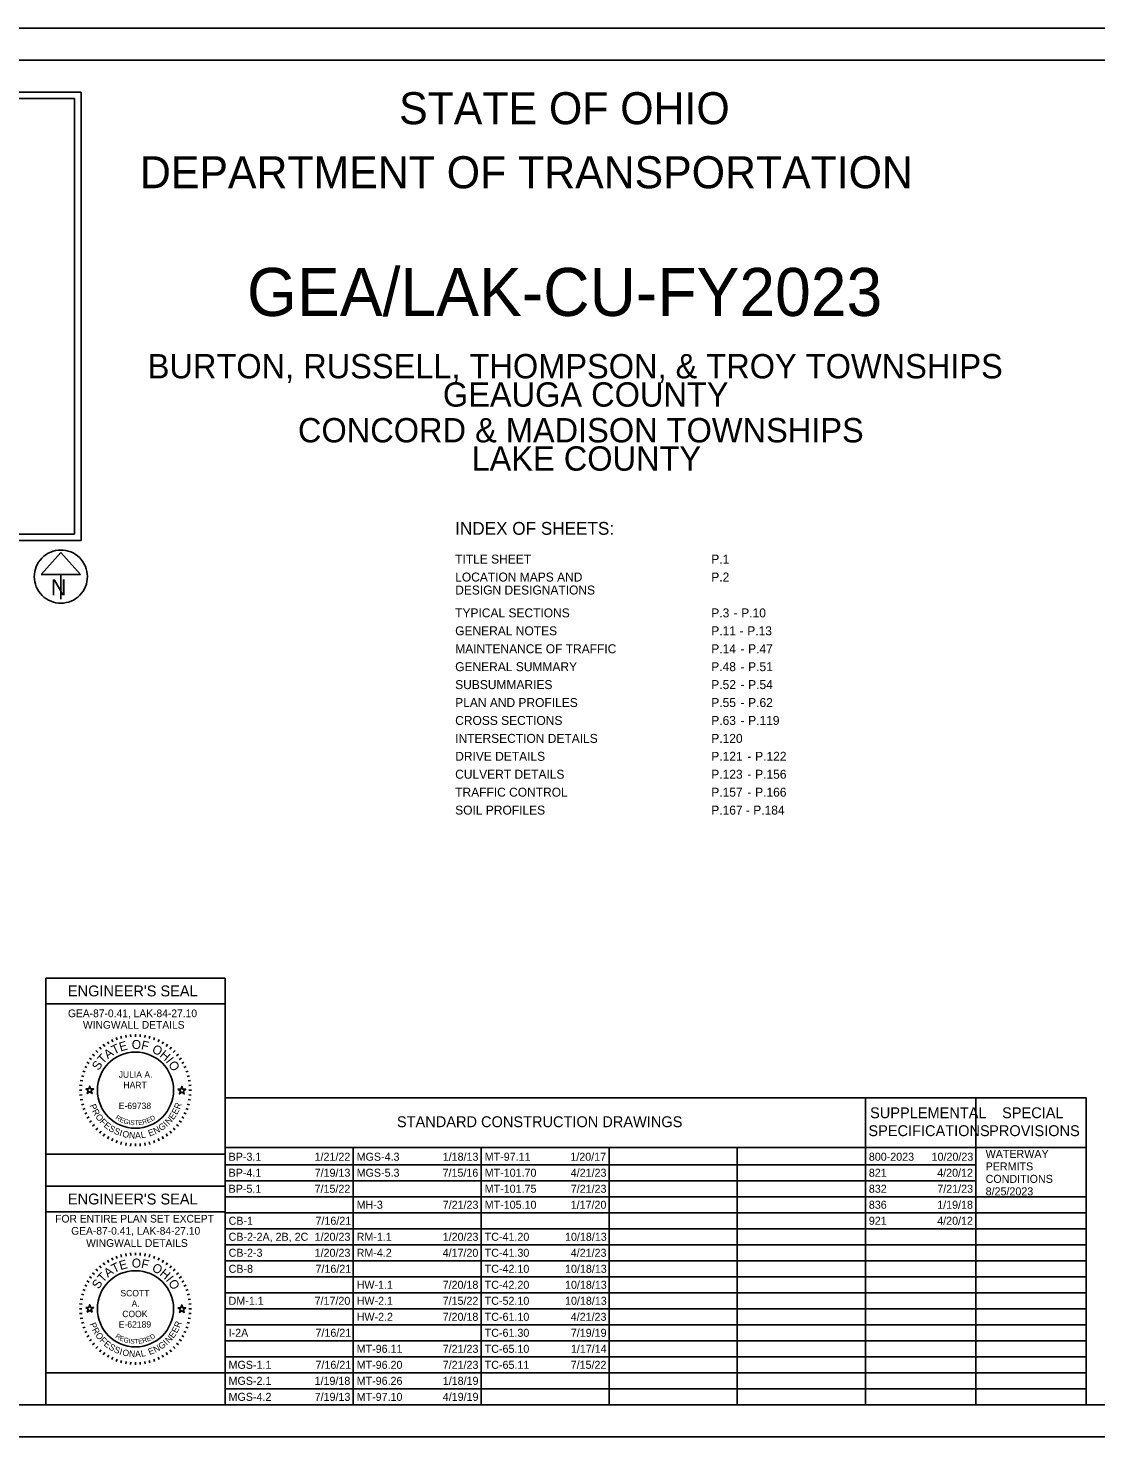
# Model space of a CAD drawing. Extents: x -0.3 to 41.5, y 0 to 22.
# Drawn here: x 8.17 to 24.85, y 0 to 22 of the extents above; entities that cross this region are included whole.
import ezdxf

# ---------------------------------------------------------------- set-up
doc = ezdxf.new("R2010")
doc.units = 0
for name, color, linetype in [('GM_X_Section', 7, 'Continuous'), ('SH_Border', 7, 'Continuous'), ('SH_Cut_Line', 7, 'Continuous'), ('SH_Data', 7, 'Continuous')]:
    doc.layers.add(name, color=color, linetype=linetype)

msp = doc.modelspace()

# ---------------------------------------------------------------- linework, layer by layer
at = {"layer": 'SH_Border'}
msp.add_lwpolyline([(0, 0), (34, 0), (34, 22), (0, 22)], close=True, dxfattribs=at)
at = {"layer": 'SH_Cut_Line'}
for p, q in [((2, 21), (9, 21)), ((2.1, 20.9), (8.9, 20.9)), ((8.9, 20.9), (8.9, 14.1)), ((9, 21), (9, 14)), ((2.1, 14.1), (8.9, 14.1)), ((2, 14), (9, 14)), ((8.685, 13.809), (8.377, 13.468)), ((8.992, 13.468), (8.685, 13.809)), ((8.377, 13.468), (8.992, 13.468)), ((8.685, 13.468), (8.685, 13.081)), ((8.685, 13.435), (8.685, 13.435)), ((8.685, 13.435), (8.685, 13.435)), ((8.45, 3.914), (8.45, 7.164)), ((8.45, 7.164), (11.25, 7.164)), ((11.25, 7.164), (11.25, 3.914)), ((11.25, 0.5), (11.25, 7)), ((8.45, 6.764), (11.25, 6.764)), ((9.413, 6.171), (9.433, 6.137)), ((9.48, 6.207), (9.497, 6.17)), ((9.551, 6.236), (9.564, 6.198)), ((9.624, 6.259), (9.634, 6.22)), ((9.698, 6.275), (9.705, 6.236)), ((9.774, 6.285), (9.777, 6.245)), ((9.85, 6.289), (9.85, 6.249)), ((9.926, 6.285), (9.923, 6.245)), ((10.002, 6.275), (9.995, 6.236)), ((10.076, 6.259), (10.066, 6.22)), ((10.149, 6.236), (10.136, 6.198)), ((10.22, 6.207), (10.203, 6.17)), ((10.287, 6.171), (10.267, 6.137)), ((9.18, 5.976), (9.21, 5.95)), ((9.231, 6.032), (9.26, 6.004)), ((9.288, 6.084), (9.313, 6.053)), ((9.348, 6.13), (9.371, 6.098)), ((10.352, 6.13), (10.329, 6.098)), ((10.412, 6.084), (10.387, 6.053)), ((10.469, 6.032), (10.44, 6.004)), ((10.52, 5.976), (10.49, 5.95)), ((9.057, 5.783), (9.093, 5.766)), ((9.092, 5.851), (9.127, 5.831)), ((9.133, 5.915), (9.166, 5.893)), ((10.567, 5.915), (10.534, 5.893)), ((10.608, 5.851), (10.573, 5.831)), ((10.643, 5.783), (10.607, 5.766)), ((8.988, 5.566), (9.028, 5.559)), ((9.005, 5.64), (9.043, 5.63)), ((9.028, 5.713), (9.065, 5.699)), ((10.672, 5.713), (10.635, 5.699)), ((10.695, 5.64), (10.657, 5.63)), ((10.712, 5.566), (10.672, 5.559)), ((8.975, 5.414), (9.015, 5.414)), ((8.978, 5.49), (9.018, 5.486)), ((8.978, 5.337), (9.018, 5.341)), ((10.722, 5.49), (10.682, 5.486)), ((10.722, 5.337), (10.682, 5.341)), ((10.725, 5.414), (10.685, 5.414)), ((11.25, 5.292), (24.7, 5.292)), ((21.25, 0.5), (21.25, 5.292)), ((22.975, 0.5), (22.975, 5.292)), ((24.7, 0.5), (24.7, 5.292)), ((8.988, 5.262), (9.028, 5.269)), ((9.005, 5.187), (9.043, 5.197)), ((9.028, 5.114), (9.065, 5.128)), ((9.057, 5.044), (9.093, 5.061)), ((10.643, 5.044), (10.607, 5.061)), ((10.672, 5.114), (10.635, 5.128)), ((10.695, 5.187), (10.657, 5.197)), ((10.712, 5.262), (10.672, 5.269)), ((9.092, 4.976), (9.127, 4.996)), ((9.133, 4.912), (9.166, 4.935)), ((9.18, 4.851), (9.21, 4.877)), ((10.52, 4.851), (10.49, 4.877)), ((10.567, 4.912), (10.534, 4.935)), ((10.608, 4.976), (10.573, 4.996)), ((9.231, 4.795), (9.26, 4.823)), ((9.288, 4.743), (9.313, 4.774)), ((9.348, 4.697), (9.371, 4.73)), ((9.413, 4.656), (9.433, 4.69)), ((9.48, 4.621), (9.497, 4.657)), ((9.551, 4.591), (9.564, 4.629)), ((10.149, 4.591), (10.136, 4.629)), ((10.22, 4.621), (10.203, 4.657)), ((10.287, 4.656), (10.267, 4.69)), ((10.352, 4.697), (10.329, 4.73)), ((10.412, 4.743), (10.387, 4.774)), ((10.469, 4.795), (10.44, 4.823)), ((9.624, 4.568), (9.634, 4.607)), ((9.698, 4.552), (9.705, 4.591)), ((9.774, 4.542), (9.777, 4.582)), ((9.85, 4.539), (9.85, 4.579)), ((9.926, 4.542), (9.923, 4.582)), ((10.002, 4.552), (9.995, 4.591)), ((10.076, 4.568), (10.066, 4.607)), ((11.25, 4.521), (24.7, 4.521)), ((13.25, 0.5), (13.25, 4.521)), ((15.25, 0.5), (15.25, 4.521)), ((17.25, 0.5), (17.25, 4.521)), ((19.25, 0.5), (19.25, 4.521)), ((11.25, 4.25), (22.975, 4.25)), ((11.25, 4), (22.975, 4)), ((8.45, 3.914), (11.25, 3.914)), ((8.45, 0.5), (8.45, 3.914)), ((8.45, 3.914), (11.25, 3.914)), ((11.25, 3.75), (24.7, 3.75)), ((11.25, 3.75), (11.25, 0.5)), ((8.45, 3.514), (11.25, 3.514)), ((11.25, 3.5), (24.7, 3.5)), ((11.25, 3.25), (24.7, 3.25)), ((9.698, 2.862), (9.705, 2.822)), ((9.774, 2.872), (9.777, 2.832)), ((9.85, 2.875), (9.85, 2.835)), ((9.926, 2.872), (9.923, 2.832)), ((10.002, 2.862), (9.995, 2.822)), ((11.25, 3), (24.7, 3)), ((9.288, 2.67), (9.313, 2.64)), ((9.348, 2.717), (9.371, 2.684)), ((9.413, 2.758), (9.433, 2.723)), ((9.48, 2.793), (9.497, 2.757)), ((9.551, 2.822), (9.564, 2.785)), ((9.624, 2.845), (9.634, 2.807)), ((10.076, 2.845), (10.066, 2.807)), ((10.149, 2.822), (10.136, 2.785)), ((10.22, 2.793), (10.203, 2.757)), ((10.287, 2.758), (10.267, 2.723)), ((10.352, 2.717), (10.329, 2.684)), ((10.412, 2.67), (10.387, 2.64)), ((11.25, 2.75), (24.7, 2.75)), ((9.092, 2.438), (9.127, 2.418)), ((9.133, 2.502), (9.166, 2.479)), ((9.18, 2.562), (9.21, 2.537)), ((9.231, 2.619), (9.26, 2.59)), ((10.469, 2.619), (10.44, 2.59)), ((10.52, 2.562), (10.49, 2.537)), ((10.567, 2.502), (10.534, 2.479)), ((10.608, 2.438), (10.573, 2.418)), ((11.25, 2.5), (24.7, 2.5)), ((9.005, 2.226), (9.043, 2.216)), ((9.028, 2.299), (9.065, 2.286)), ((9.057, 2.37), (9.093, 2.353)), ((10.643, 2.37), (10.607, 2.353)), ((10.672, 2.299), (10.635, 2.286)), ((10.695, 2.226), (10.657, 2.216)), ((11.25, 2.25), (24.7, 2.25)), ((8.975, 2), (9.015, 2)), ((8.978, 2.076), (9.018, 2.073)), ((8.988, 2.152), (9.028, 2.145)), ((10.712, 2.152), (10.672, 2.145)), ((10.722, 2.076), (10.682, 2.073)), ((10.725, 2), (10.685, 2)), ((11.25, 2), (24.7, 2)), ((8.978, 1.924), (9.018, 1.927)), ((8.988, 1.848), (9.028, 1.855)), ((9.005, 1.774), (9.043, 1.784)), ((10.695, 1.774), (10.657, 1.784)), ((10.712, 1.848), (10.672, 1.855)), ((10.722, 1.924), (10.682, 1.927)), ((9.028, 1.701), (9.065, 1.714)), ((9.057, 1.63), (9.093, 1.647)), ((9.092, 1.562), (9.127, 1.583)), ((10.608, 1.562), (10.573, 1.583)), ((10.643, 1.63), (10.607, 1.647)), ((10.672, 1.701), (10.635, 1.714)), ((11.25, 1.75), (24.7, 1.75)), ((9.133, 1.498), (9.166, 1.521)), ((9.18, 1.438), (9.21, 1.463)), ((9.231, 1.381), (9.26, 1.41)), ((9.288, 1.33), (9.313, 1.36)), ((10.412, 1.33), (10.387, 1.36)), ((10.469, 1.381), (10.44, 1.41)), ((10.52, 1.438), (10.49, 1.463)), ((10.567, 1.498), (10.534, 1.521)), ((11.25, 1.5), (24.7, 1.5)), ((9.348, 1.283), (9.371, 1.316)), ((9.413, 1.242), (9.433, 1.277)), ((9.48, 1.207), (9.497, 1.243)), ((9.551, 1.178), (9.564, 1.215)), ((9.624, 1.155), (9.634, 1.193)), ((9.698, 1.138), (9.705, 1.178)), ((9.774, 1.128), (9.777, 1.168)), ((9.85, 1.125), (9.85, 1.165)), ((9.926, 1.128), (9.923, 1.168)), ((10.002, 1.138), (9.995, 1.178)), ((10.076, 1.155), (10.066, 1.193)), ((10.149, 1.178), (10.136, 1.215)), ((10.22, 1.207), (10.203, 1.243)), ((10.287, 1.242), (10.267, 1.277)), ((10.352, 1.283), (10.329, 1.316)), ((11.25, 1.25), (24.7, 1.25)), ((11.25, 1), (24.7, 1)), ((11.25, 0.75), (24.7, 0.75)), ((8.45, 0.5), (11.25, 0.5))]:
    msp.add_line(p, q, dxfattribs=at)
for points in [[(9.074, 5.434), (9.121, 5.434), (9.135, 5.478), (9.149, 5.434), (9.196, 5.434), (9.158, 5.406), (9.173, 5.361), (9.135, 5.389), (9.097, 5.361), (9.112, 5.406)], [(10.513, 5.428), (10.56, 5.428), (10.574, 5.473), (10.589, 5.428), (10.635, 5.428), (10.598, 5.401), (10.612, 5.356), (10.574, 5.384), (10.536, 5.356), (10.551, 5.401)], [(8.45, 3.914), (8.45, 4.414), (11.25, 4.414), (11.25, 3.914)], [(9.074, 2.02), (9.121, 2.02), (9.135, 2.065), (9.149, 2.02), (9.196, 2.02), (9.158, 1.992), (9.173, 1.948), (9.135, 1.975), (9.097, 1.948), (9.112, 1.992)], [(10.513, 2.015), (10.56, 2.015), (10.574, 2.059), (10.589, 2.015), (10.635, 2.015), (10.598, 1.987), (10.612, 1.942), (10.574, 1.97), (10.536, 1.942), (10.551, 1.987)], [(8.45, 0.5), (8.45, 1), (11.25, 1), (11.25, 0.5)]]:
    msp.add_lwpolyline(points, close=True, dxfattribs=at)
for centre in [(9.85, 5.414), (9.85, 2)]:
    msp.add_circle(centre, 0.595, dxfattribs=at)
msp.add_arc((8.685, 13.435), 0.415, 129.7798, 129.7633, dxfattribs=at)
at = {"layer": 'SH_Data'}
msp.add_lwpolyline([(1.5, 21.5), (33.5, 21.5), (33.5, 0.5), (1.5, 0.5)], close=True, dxfattribs=at)

# ---------------------------------------------------------------- texts
at = {"layer": 'GM_X_Section'}
for s, height, p in [('STATE OF OHIO', 0.5, (13.968, 20.5)), ('DEPARTMENT OF TRANSPORTATION', 0.5, (9.92, 19.5)), ('GEA/LAK-CU-FY2023', 0.75, (11.592, 17.505)), ('BURTON, RUSSELL, THOMPSON, & TROY TOWNSHIPS', 0.38, (10.042, 16.531)), ('GEAUGA COUNTY', 0.38, (14.652, 16.089)), ('CONCORD & MADISON TOWNSHIPS', 0.38, (12.388, 15.531)), ('LAKE COUNTY', 0.38, (15.099, 15.089)), ('INDEX OF SHEETS:', 0.2, (14.844, 14.088)), ('TITLE SHEET', 0.14, (14.844, 13.638)), ('P.1', 0.14, (18.844, 13.638)), ('LOCATION MAPS AND', 0.14, (14.844, 13.358)), ('P.2', 0.14, (18.844, 13.358)), ('DESIGN DESIGNATIONS', 0.14, (14.844, 13.155)), ('TYPICAL SECTIONS', 0.14, (14.844, 12.798)), ('P.3', 0.14, (18.844, 12.798)), (' - ', 0.14, (19.138, 12.798)), ('P.10', 0.14, (19.312, 12.798)), ('GENERAL NOTES', 0.14, (14.844, 12.518)), ('P.11', 0.14, (18.844, 12.518)), (' - ', 0.14, (19.232, 12.518)), ('P.13', 0.14, (19.406, 12.518)), ('MAINTENANCE OF TRAFFIC', 0.14, (14.844, 12.238)), ('P.14', 0.14, (18.844, 12.238)), ('P.47', 0.14, (19.42, 12.238)), (' - ', 0.14, (19.247, 12.238)), ('GENERAL SUMMARY', 0.14, (14.844, 11.958)), ('P.48', 0.14, (18.844, 11.958)), (' - ', 0.14, (19.247, 11.958)), ('P.51', 0.14, (19.42, 11.958)), ('SUBSUMMARIES', 0.14, (14.844, 11.678)), ('P.52', 0.14, (18.844, 11.678)), (' - ', 0.14, (19.247, 11.678)), ('P.54', 0.14, (19.42, 11.678)), ('PLAN AND PROFILES', 0.14, (14.844, 11.398)), ('P.55', 0.14, (18.844, 11.398)), (' - ', 0.14, (19.247, 11.398)), ('P.62', 0.14, (19.42, 11.398)), ('CROSS SECTIONS', 0.14, (14.844, 11.118)), ('P.63', 0.14, (18.844, 11.118)), ('P.119', 0.14, (19.42, 11.118)), (' - ', 0.14, (19.247, 11.118)), ('INTERSECTION DETAILS', 0.14, (14.844, 10.838)), ('P.120', 0.14, (18.844, 10.838)), ('DRIVE DETAILS', 0.14, (14.844, 10.558)), ('P.121', 0.14, (18.844, 10.558)), (' - ', 0.14, (19.355, 10.558)), ('P.122', 0.14, (19.529, 10.558)), ('CULVERT DETAILS', 0.14, (14.844, 10.278)), ('P.123', 0.14, (18.844, 10.278)), ('P.156', 0.14, (19.529, 10.278)), ('TRAFFIC CONTROL', 0.14, (14.844, 9.998)), ('P.157', 0.14, (18.844, 9.998)), (' - ', 0.14, (19.355, 10.278)), ('P.166', 0.14, (19.529, 9.998)), (' - ', 0.14, (19.355, 9.998)), ('SOIL PROFILES', 0.14, (14.844, 9.718)), ('P.167 - P.184', 0.14, (18.844, 9.718)), ('SUPPLEMENTAL', 0.17, (21.324, 4.976)), ('SPECIAL', 0.17, (23.386, 4.976)), ('STANDARD CONSTRUCTION DRAWINGS', 0.17, (13.934, 4.836)), ('SPECIFICATIONS', 0.17, (21.298, 4.696)), ('PROVISIONS', 0.17, (23.184, 4.696)), ('FOR ENTIRE PLAN SET EXCEPT', 0.12, (8.597, 3.347)), ('GEA-87-0.41, LAK-84-27.10', 0.12, (8.846, 3.157)), ('WINGWALL DETAILS', 0.12, (9.08, 2.967))]:
    msp.add_text(s, height=height, dxfattribs=at).set_placement(p)
at = {"layer": 'SH_Cut_Line'}
for s, height, p in [('N', 0.25, (8.529, 13.144)), ("ENGINEER'S SEAL", 0.17, (8.795, 6.879)), ('GEA-87-0.41, LAK-84-27.10', 0.12, (8.796, 6.554)), ('WINGWALL DETAILS', 0.12, (9.03, 6.374)), ('JULIA A.', 0.1, (9.588, 5.607)), ('HART', 0.1, (9.662, 5.445)), ('E-69738', 0.1, (9.589, 5.12)), ('BP-3.1', 0.125, (11.305, 4.312)), ('1/21/22', 0.125, (12.648, 4.312)), ('MGS-4.3', 0.125, (13.305, 4.312)), ('1/18/13', 0.125, (14.649, 4.312)), ('MT-97.11', 0.125, (15.305, 4.312)), ('1/20/17', 0.125, (16.643, 4.312)), ('800-2023', 0.125, (21.305, 4.312)), ('10/20/23', 0.125, (22.285, 4.312)), ('WATERWAY ', 0.125, (23.129, 4.356)), ('BP-4.1', 0.125, (11.305, 4.062)), ('7/19/13', 0.125, (12.649, 4.062)), ('MGS-5.3', 0.125, (13.305, 4.062)), ('7/15/16', 0.125, (14.647, 4.062)), ('MT-101.70', 0.125, (15.305, 4.062)), ('4/21/23', 0.125, (16.649, 4.062)), ('821', 0.125, (21.305, 4.062)), ('4/20/12', 0.125, (22.373, 4.062)), ('PERMITS', 0.125, (23.129, 4.161)), ('CONDITIONS', 0.125, (23.129, 3.966)), ("ENGINEER'S SEAL", 0.17, (8.795, 3.629)), ('BP-5.1', 0.125, (11.305, 3.812)), ('7/15/22', 0.125, (12.648, 3.812)), ('MT-101.75', 0.125, (15.305, 3.812)), ('7/21/23', 0.125, (16.649, 3.812)), ('832', 0.125, (21.305, 3.812)), ('7/21/23', 0.125, (22.374, 3.812)), ('8/25/2023', 0.125, (23.129, 3.771)), ('MH-3', 0.125, (13.305, 3.562)), ('7/21/23', 0.125, (14.649, 3.562)), ('MT-105.10', 0.125, (15.305, 3.562)), ('1/17/20', 0.125, (16.648, 3.562)), ('836', 0.125, (21.305, 3.562)), ('1/19/18', 0.125, (22.373, 3.562)), ('CB-1', 0.125, (11.305, 3.312)), ('7/16/21', 0.125, (12.662, 3.312)), ('921', 0.125, (21.305, 3.312)), ('4/20/12', 0.125, (22.373, 3.312)), ('CB-2-2A, 2B, 2C', 0.125, (11.305, 3.062)), ('1/20/23', 0.125, (12.649, 3.062)), ('RM-1.1', 0.125, (13.305, 3.062)), ('1/20/23', 0.125, (14.649, 3.062)), ('TC-41.20', 0.125, (15.305, 3.062)), ('10/18/13', 0.125, (16.56, 3.062)), ('CB-2-3', 0.125, (11.305, 2.812)), ('1/20/23', 0.125, (12.649, 2.812)), ('RM-4.2', 0.125, (13.305, 2.812)), ('4/17/20', 0.125, (14.648, 2.812)), ('TC-41.30', 0.125, (15.305, 2.812)), ('4/21/23', 0.125, (16.649, 2.812)), ('CB-8', 0.125, (11.305, 2.562)), ('7/16/21', 0.125, (12.662, 2.562)), ('TC-42.10', 0.125, (15.305, 2.562)), ('10/18/13', 0.125, (16.56, 2.562)), ('HW-1.1', 0.125, (13.305, 2.312)), ('7/20/18', 0.125, (14.648, 2.312)), ('TC-42.20', 0.125, (15.305, 2.312)), ('10/18/13', 0.125, (16.56, 2.312)), ('SCOTT', 0.1, (9.615, 2.194)), ('A.', 0.1, (9.79, 2.031)), ('DM-1.1', 0.125, (11.305, 2.062)), ('7/17/20', 0.125, (12.648, 2.062)), ('HW-2.1', 0.125, (13.305, 2.062)), ('7/15/22', 0.125, (14.648, 2.062)), ('TC-52.10', 0.125, (15.305, 2.062)), ('10/18/13', 0.125, (16.56, 2.062)), ('E-62189', 0.1, (9.589, 1.706)), ('COOK', 0.1, (9.644, 1.869)), ('HW-2.2', 0.125, (13.305, 1.812)), ('7/20/18', 0.125, (14.648, 1.812)), ('TC-61.10', 0.125, (15.305, 1.812)), ('4/21/23', 0.125, (16.649, 1.812)), ('I-2A', 0.125, (11.305, 1.562)), ('7/16/21', 0.125, (12.662, 1.562)), ('TC-61.30', 0.125, (15.305, 1.562)), ('7/19/19', 0.125, (16.65, 1.562)), ('MT-96.11', 0.125, (13.305, 1.312)), ('7/21/23', 0.125, (14.649, 1.312)), ('TC-65.10', 0.125, (15.305, 1.312)), ('1/17/14', 0.125, (16.651, 1.312)), ('MGS-1.1', 0.125, (11.305, 1.062)), ('7/16/21', 0.125, (12.662, 1.062)), ('MT-96.20', 0.125, (13.305, 1.062)), ('7/21/23', 0.125, (14.649, 1.062)), ('TC-65.11', 0.125, (15.305, 1.062)), ('7/15/22', 0.125, (16.648, 1.062)), ('MGS-2.1', 0.125, (11.305, 0.812)), ('1/19/18', 0.125, (12.648, 0.812)), ('MT-96.26', 0.125, (13.305, 0.812)), ('1/18/19', 0.125, (14.65, 0.812)), ('MGS-4.2', 0.125, (11.305, 0.562)), ('7/19/13', 0.125, (12.649, 0.562)), ('MT-97.10', 0.125, (13.305, 0.562)), ('4/19/19', 0.125, (14.65, 0.562))]:
    msp.add_text(s, height=height, dxfattribs=at).set_placement(p)
for s, height, rotation, p in [('E', 0.14, 15.7571, (9.617, 6.017)), ('O', 0.14, 359.7812, (9.792, 6.058)), ('F', 0.14, 347.4362, (9.931, 6.055)), ('T', 0.14, 46.4344, (9.342, 5.814)), ('A', 0.14, 36.4747, (9.419, 5.895)), ('T', 0.14, 25.7167, (9.516, 5.968)), ('O', 0.14, 332.2586, (10.096, 6.012)), ('H', 0.14, 319.9136, (10.218, 5.945)), ('S', 0.14, 57.1924, (9.276, 5.712)), ('I', 0.14, 308.367, (10.317, 5.861)), ('O', 0.14, 303.1491, (10.356, 5.816)), ('P', 0.1, 291.494, (9.132, 5.175)), ('R', 0.1, 298.7311, (9.168, 5.087)), ('E', 0.1, 54.758, (10.443, 4.944)), ('E', 0.1, 61.9951, (10.497, 5.023)), ('R', 0.1, 69.2322, (10.541, 5.107)), ('O', 0.1, 306.4666, (9.218, 4.998)), ('F', 0.1, 314.7068, (9.284, 4.912)), ('E', 0.1, 321.4393, (9.347, 4.849)), ('S', 0.1, 328.6764, (9.422, 4.79)), ('R', 0.075, 327.8239, (9.53, 4.968)), ('E', 0.075, 337.7777, (9.594, 4.926)), ('G', 0.075, 344.2727, (9.658, 4.898)), ('I', 0.075, 350.6464, (9.737, 4.877)), ('S', 0.075, 353.7858, (9.765, 4.872)), ('T', 0.075, 3.0061, (9.835, 4.864)), ('E', 0.075, 8.9826, (9.899, 4.867)), ('R', 0.075, 17.6836, (9.969, 4.876)), ('E', 0.075, 23.3052, (10.041, 4.899)), ('D', 0.075, 31.466, (10.105, 4.927)), ('N', 0.1, 27.3113, (10.16, 4.724)), ('G', 0.1, 35.0469, (10.25, 4.772)), ('I', 0.1, 43.287, (10.338, 4.836)), ('N', 0.1, 47.0224, (10.374, 4.869)), ('S', 0.1, 335.9134, (9.504, 4.741)), ('I', 0.1, 343.1505, (9.592, 4.703)), ('O', 0.1, 346.8859, (9.638, 4.688)), ('N', 0.1, 355.1261, (9.745, 4.665)), ('A', 0.1, 2.8617, (9.846, 4.657)), ('L', 0.1, 10.0987, (9.942, 4.663)), ('E', 0.1, 20.0742, (10.07, 4.69)), ('T', 0.14, 25.7167, (9.516, 2.554)), ('E', 0.14, 15.7571, (9.617, 2.603)), ('O', 0.14, 359.7812, (9.792, 2.644)), ('F', 0.14, 347.4362, (9.931, 2.642)), ('O', 0.14, 332.2586, (10.096, 2.598)), ('S', 0.14, 57.1924, (9.276, 2.298)), ('T', 0.14, 46.4344, (9.342, 2.4)), ('A', 0.14, 36.4747, (9.419, 2.482)), ('H', 0.14, 319.9136, (10.218, 2.532)), ('I', 0.14, 308.367, (10.317, 2.447)), ('O', 0.14, 303.1491, (10.356, 2.403)), ('P', 0.1, 291.494, (9.132, 1.762)), ('R', 0.1, 69.2322, (10.541, 1.694)), ('R', 0.1, 298.7311, (9.168, 1.673)), ('O', 0.1, 306.4666, (9.218, 1.585)), ('F', 0.1, 314.7068, (9.284, 1.498)), ('R', 0.075, 327.8239, (9.53, 1.554)), ('E', 0.075, 337.7777, (9.594, 1.513)), ('G', 0.075, 344.2727, (9.658, 1.485)), ('R', 0.075, 17.6836, (9.969, 1.463)), ('E', 0.075, 23.3052, (10.041, 1.486)), ('D', 0.075, 31.466, (10.105, 1.514)), ('N', 0.1, 47.0224, (10.374, 1.455)), ('E', 0.1, 54.758, (10.443, 1.531)), ('E', 0.1, 61.9951, (10.497, 1.609)), ('E', 0.1, 321.4393, (9.347, 1.435)), ('S', 0.1, 328.6764, (9.422, 1.377)), ('S', 0.1, 335.9134, (9.504, 1.328)), ('I', 0.1, 343.1505, (9.592, 1.289)), ('O', 0.1, 346.8859, (9.638, 1.274)), ('I', 0.075, 350.6464, (9.737, 1.463)), ('N', 0.1, 355.1261, (9.745, 1.251)), ('S', 0.075, 353.7858, (9.765, 1.458)), ('T', 0.075, 3.0061, (9.835, 1.451)), ('A', 0.1, 2.8617, (9.846, 1.244)), ('E', 0.075, 8.9826, (9.899, 1.453)), ('L', 0.1, 10.0987, (9.942, 1.249)), ('E', 0.1, 20.0742, (10.07, 1.277)), ('N', 0.1, 27.3113, (10.16, 1.31)), ('G', 0.1, 35.0469, (10.25, 1.358)), ('I', 0.1, 43.287, (10.338, 1.422))]:
    msp.add_text(s, height=height, rotation=rotation, dxfattribs=at).set_placement(p)

doc.saveas('drawing.dxf')
